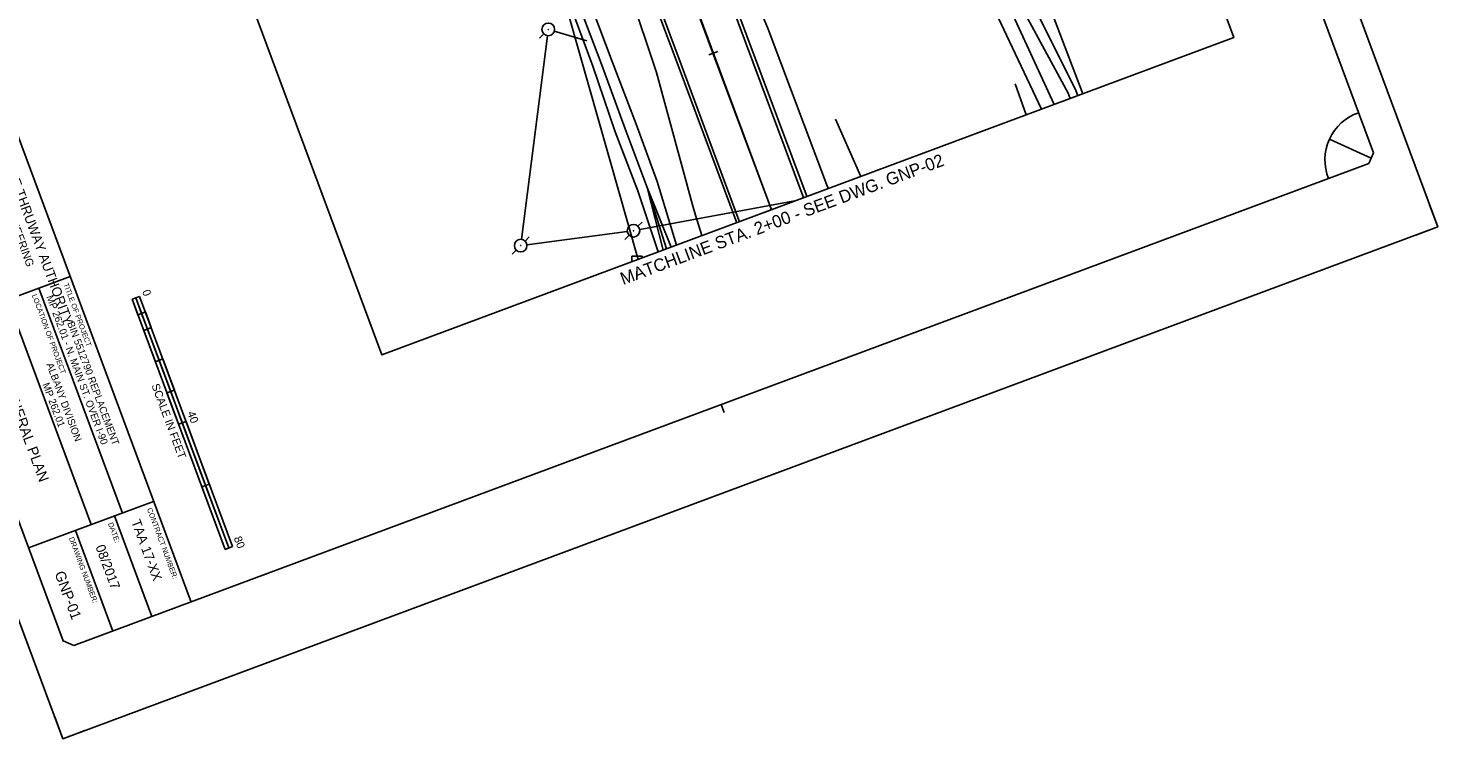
# Model space of a CAD drawing. Extents: x 1040172 to 1040822, y 1127790 to 1128580.
# Drawn here: x 1040398.7 to 1040821.5, y 1127789.6 to 1128002.5 of the extents above; entities that cross this region are included whole.
import ezdxf

# ---------------------------------------------------------------- set-up
doc = ezdxf.new("R2010")
doc.units = 0
for name, color, linetype in [('AC_P', 7, 'Continuous'), ('ACSRT_P', 7, 'Continuous'), ('clip boundary', 7, 'Continuous'), ('DD', 7, 'Continuous'), ('DELB', 7, 'Continuous'), ('LABL', 7, 'Continuous'), ('LELB', 7, 'Continuous'), ('MHB', 7, 'Continuous'), ('MPM', 7, 'Continuous'), ('NML_P', 7, 'Continuous'), ('NML_P_T', 7, 'Continuous'), ('NSB_P', 7, 'Continuous'), ('O_Details_Text Title and Subtitle Proposed_P_T', 7, 'Continuous'), ('PE', 7, 'Continuous'), ('RDU', 7, 'Continuous'), ('SHEET_BORDER', 7, 'Continuous'), ('SHEET_BORDER_CUT', 7, 'Continuous'), ('SHEET_BORDER_TEXT', 7, 'Continuous'), ('STPBY', 7, 'Continuous'), ('STSEW', 7, 'Continuous'), ('UEO', 7, 'Continuous'), ('UP', 7, 'Continuous'), ('UPGW', 7, 'Continuous')]:
    doc.layers.add(name, color=color, linetype=linetype)

msp = doc.modelspace()

# ---------------------------------------------------------------- linework, layer by layer
at = {"layer": 'AC_P'}
msp.add_line((1040551.95, 1128135.59), (1040621.67, 1127948.13), dxfattribs=at)
at = {"layer": 'ACSRT_P'}
for points in [[(1040605.59, 1127995.5), (1040602.89, 1127994.5)], [(1040623.92, 1127948.97), (1040619.42, 1127947.3)]]:
    msp.add_lwpolyline(points, dxfattribs=at)
at = {"layer": 'clip boundary'}
for points in [[(1040584.48, 1128580.33), (1040821.52, 1127942.99), (1040409.12, 1127789.61), (1040172.08, 1128426.95)], [(1040311.42, 1128424.61), (1040504.79, 1127904.67), (1040760.34, 1127999.71), (1040566.96, 1128519.66)]]:
    msp.add_lwpolyline(points, close=True, dxfattribs=at)
at = {"layer": 'DD'}
msp.add_lwpolyline([(1040590.16, 1127936.41), (1040584.34, 1127954.8), (1040577.73, 1127972.42), (1040570.66, 1127991.71), (1040562.32, 1128013.81), (1040557.05, 1128034.44), (1040549.61, 1128054.25), (1040542.46, 1128077.69), (1040533.08, 1128100.98), (1040522.95, 1128126.72), (1040518.21, 1128143.72), (1040509.19, 1128174.67), (1040500.96, 1128197.49), (1040493.5, 1128216.61), (1040486.01, 1128239.31), (1040476.77, 1128264.06), (1040465.21, 1128292.91), (1040456.76, 1128312.61), (1040439.7, 1128341.45), (1040438.14, 1128345.77)], dxfattribs=at)
at = {"layer": 'DELB'}
for points in [[(1040702.66, 1127978.26), (1040686.91, 1128011.53), (1040691.97, 1128016.01), (1040697.9, 1128014.08), (1040712.9, 1127984.14), (1040713.54, 1127982.3)], [(1040706.5, 1127979.69), (1040692.31, 1128010.21), (1040693.73, 1128012), (1040695.25, 1128011.56), (1040710.7, 1127983.05), (1040711.25, 1127981.45)]]:
    msp.add_lwpolyline(points, dxfattribs=at)
at = {"layer": 'LABL'}
msp.add_lwpolyline([(1040425.91, 1128368.18), (1040444.53, 1128309.71), (1040463.02, 1128257.15), (1040477.81, 1128216.23), (1040494.07, 1128178.95), (1040522.79, 1128098.94), (1040535.3, 1128073.89), (1040559.97, 1128013.01), (1040568.12, 1127991.17), (1040574.76, 1127971.48), (1040581.61, 1127953.82), (1040587.68, 1127935.49)], dxfattribs=at)
at = {"layer": 'LELB'}
for points in [[(1040593.2, 1127937.55), (1040587.34, 1127956.62), (1040581.09, 1127973.78), (1040573.86, 1127992.53), (1040565.61, 1128014.66), (1040560.09, 1128035.33), (1040553.1, 1128055.45), (1040545.54, 1128078.74), (1040536.49, 1128101.98), (1040528.25, 1128126.98), (1040521.57, 1128144.94), (1040511.66, 1128175.43), (1040503.47, 1128198.65), (1040496.47, 1128217.58), (1040488.54, 1128240.6), (1040478.6, 1128264.98), (1040468.18, 1128294)], [(1040587.68, 1127935.49), (1040581.61, 1127953.82), (1040574.76, 1127971.48), (1040568.12, 1127991.17), (1040559.97, 1128013.01), (1040554.52, 1128033.3)], [(1040589.16, 1127936.04), (1040584.34, 1127954.8)], [(1040591.53, 1127936.92), (1040584.34, 1127954.8)]]:
    msp.add_lwpolyline(points, dxfattribs=at)
at = {"layer": 'MHB'}
for points in [[(1040581.63, 1127933.24), (1040555, 1128027.07), (1040529.93, 1128094.57), (1040509.19, 1128193.54)], [(1040594.84, 1128145.74), (1040609.62, 1128124.16), (1040630.41, 1128039.61), (1040689.32, 1128050.28), (1040715.1, 1127982.88)]]:
    msp.add_lwpolyline(points, dxfattribs=at)
at = {"layer": 'MPM'}
for p, q in [((1040579.77, 1127932.55), (1040579.77, 1127934.24)), ((1040579.77, 1127934.24), (1040582.92, 1127934.24)), ((1040582.92, 1127934.24), (1040582.92, 1127933.72))]:
    msp.add_line(p, q, dxfattribs=at)
at = {"layer": 'NML_P'}
msp.add_line((1040504.79, 1127904.67), (1040760.34, 1127999.71), dxfattribs=at)
at = {"layer": 'NSB_P'}
for p, q in [((1040429.88, 1127921.35), (1040432.13, 1127922.18)), ((1040431.01, 1127921.76), (1040429.88, 1127921.35)), ((1040429.88, 1127921.35), (1040457.77, 1127846.36)), ((1040429.88, 1127921.35), (1040431.63, 1127916.66)), ((1040431.01, 1127921.76), (1040458.9, 1127846.78)), ((1040432.75, 1127917.08), (1040431.01, 1127921.76)), ((1040432.13, 1127922.18), (1040460.02, 1127847.2)), ((1040431.63, 1127916.66), (1040433.88, 1127917.5)), ((1040433.88, 1127917.5), (1040432.75, 1127917.08)), ((1040435.62, 1127912.81), (1040433.88, 1127917.5)), ((1040431.63, 1127916.66), (1040432.75, 1127917.08)), ((1040432.75, 1127917.08), (1040434.49, 1127912.39)), ((1040433.37, 1127911.97), (1040435.62, 1127912.81)), ((1040434.49, 1127912.39), (1040433.37, 1127911.97)), ((1040433.37, 1127911.97), (1040436.86, 1127902.6)), ((1040434.49, 1127912.39), (1040435.62, 1127912.81)), ((1040437.98, 1127903.02), (1040434.49, 1127912.39)), ((1040436.86, 1127902.6), (1040439.11, 1127903.44)), ((1040436.86, 1127902.6), (1040437.98, 1127903.02)), ((1040439.11, 1127903.44), (1040437.98, 1127903.02)), ((1040437.98, 1127903.02), (1040441.47, 1127893.65)), ((1040442.59, 1127894.06), (1040439.11, 1127903.44)), ((1040440.34, 1127893.23), (1040442.59, 1127894.06)), ((1040441.47, 1127893.65), (1040440.34, 1127893.23)), ((1040440.34, 1127893.23), (1040443.83, 1127883.85)), ((1040441.47, 1127893.65), (1040442.59, 1127894.06)), ((1040444.95, 1127884.27), (1040441.47, 1127893.65)), ((1040443.83, 1127883.85), (1040446.08, 1127884.69)), ((1040443.83, 1127883.85), (1040444.95, 1127884.27)), ((1040446.08, 1127884.69), (1040444.95, 1127884.27)), ((1040444.95, 1127884.27), (1040451.92, 1127865.53)), ((1040453.05, 1127865.95), (1040446.08, 1127884.69)), ((1040450.8, 1127865.11), (1040453.05, 1127865.95)), ((1040451.92, 1127865.53), (1040450.8, 1127865.11)), ((1040450.8, 1127865.11), (1040457.77, 1127846.36)), ((1040451.92, 1127865.53), (1040453.05, 1127865.95)), ((1040458.9, 1127846.78), (1040451.92, 1127865.53)), ((1040457.77, 1127846.36), (1040460.02, 1127847.2)), ((1040457.77, 1127846.36), (1040458.9, 1127846.78))]:
    msp.add_line(p, q, dxfattribs=at)
at = {"layer": 'PE'}
for points in [[(1040439.24, 1128472.16), (1040441.33, 1128466.57), (1040458.94, 1128419.35), (1040476.26, 1128371.77), (1040493.04, 1128326.48), (1040510.61, 1128278.87), (1040527.62, 1128233.22), (1040545.23, 1128186.41), (1040562.42, 1128139.9), (1040579.67, 1128093.09), (1040596.97, 1128046.17), (1040614.6, 1127999.47), (1040632.03, 1127952.66), (1040632.25, 1127952.07)], [(1040611.22, 1127944.25), (1040611.04, 1127944.71), (1040593.69, 1127991.31), (1040575.95, 1128038.43), (1040558.63, 1128085.25), (1040541.53, 1128131.54), (1040524.14, 1128178.42), (1040506.77, 1128224.73), (1040489.58, 1128270.79), (1040472.04, 1128318.16), (1040455.43, 1128363.98), (1040438.41, 1128410.32), (1040420.58, 1128458.47), (1040418.37, 1128464.39)]]:
    msp.add_lwpolyline(points, dxfattribs=at)
at = {"layer": 'RDU'}
for points in [[(1040442.34, 1128473.31), (1040444.42, 1128467.6), (1040461.41, 1128420.47), (1040479.69, 1128373.54), (1040484.11, 1128363.91), (1040487.49, 1128353.45), (1040496.23, 1128327.89), (1040514.27, 1128279.94), (1040530.58, 1128234.37), (1040548.36, 1128187.4), (1040565.14, 1128141.04), (1040582.73, 1128094.4), (1040600.59, 1128047.69), (1040609.21, 1128026.55), (1040611.78, 1128023.8), (1040620.64, 1128002.21), (1040638.45, 1127955.04), (1040638.78, 1127954.5)], [(1040600.82, 1127940.38), (1040598.84, 1127946.51), (1040597.95, 1127949.62), (1040587.15, 1127989.28), (1040571.28, 1128036.76), (1040553.79, 1128083.5), (1040537.46, 1128130.34), (1040520.2, 1128176.84), (1040503.11, 1128223.36), (1040485.75, 1128269.45), (1040468.45, 1128317.03), (1040451.55, 1128362.66), (1040435.14, 1128409.38), (1040417.07, 1128457.26), (1040414.87, 1128463.09)]]:
    msp.add_lwpolyline(points, dxfattribs=at)
at = {"layer": 'SHEET_BORDER'}
for p, q in [((1040447.57, 1127830.58), (1040330.5, 1128145.33)), ((1040417.6, 1127853.77), (1040367.49, 1127988.51)), ((1040411.29, 1127928.11), (1040373.8, 1127914.17)), ((1040426.97, 1127857.26), (1040401.92, 1127924.63)), ((1040606.61, 1127889.73), (1040607.48, 1127887.39)), ((1040398.85, 1127846.8), (1040436.35, 1127860.75)), ((1040435.85, 1127826.22), (1040424.63, 1127856.39)), ((1040424.13, 1127821.86), (1040412.91, 1127852.03))]:
    msp.add_line(p, q, dxfattribs=at)
msp.add_lwpolyline([(1040412.42, 1127817.51), (1040409.2, 1127818.98), (1040191.33, 1128404.77), (1040192.81, 1128407.99), (1040581.19, 1128552.44), (1040584.4, 1128550.96), (1040802.27, 1127965.17), (1040800.8, 1127961.95)], close=True, dxfattribs=at)
msp.add_lwpolyline([(1040801.54, 1127963.56), (1040789.22, 1127969.2)], dxfattribs=at)
msp.add_arc((1040802.45, 1127963.14), 14.79, 108.3228, 202.4794, dxfattribs=at)
at = {"layer": 'SHEET_BORDER_CUT'}
msp.add_lwpolyline([(1040172.08, 1128426.95), (1040409.12, 1127789.61), (1040821.52, 1127942.99), (1040584.48, 1128580.33)], close=True, dxfattribs=at)
for points in [[(1040819.06, 1127949.61), (1040821.52, 1127942.99), (1040814.9, 1127940.52)], [(1040415.75, 1127792.07), (1040409.12, 1127789.61), (1040406.66, 1127796.23)]]:
    msp.add_lwpolyline(points, dxfattribs=at)
at = {"layer": 'SHEET_BORDER_TEXT'}
msp.add_line((1040409.12, 1127789.61), (1040409.12, 1127789.61), dxfattribs=at)
at = {"layer": 'STPBY'}
msp.add_lwpolyline([(1040621.67, 1127948.13), (1040621.55, 1127948.45), (1040603.98, 1127995.3), (1040586.61, 1128042.26), (1040569.27, 1128089.08), (1040551.95, 1128135.59), (1040534.57, 1128182.32), (1040517.18, 1128229.1), (1040500.26, 1128274.64), (1040482.6, 1128322.04), (1040465.84, 1128367.81), (1040448.53, 1128414.76), (1040430.74, 1128462.77), (1040428.7, 1128468.23)], dxfattribs=at)
at = {"layer": 'STSEW'}
for points in [[(1040438.27, 1128471.79), (1040440.35, 1128466.17), (1040457.9, 1128418.91), (1040475.34, 1128371.42), (1040492.13, 1128326.1), (1040509.73, 1128278.49), (1040526.79, 1128232.92), (1040544.25, 1128186.02), (1040561.46, 1128139.5), (1040578.77, 1128092.69), (1040596.13, 1128045.88), (1040613.59, 1127999.12), (1040631.02, 1127952.26), (1040631.23, 1127951.69)], [(1040612.07, 1127944.56), (1040611.89, 1127945.04), (1040594.53, 1127991.69), (1040577, 1128038.8), (1040559.65, 1128085.64), (1040542.56, 1128131.85), (1040525.02, 1128178.93), (1040507.92, 1128225.11), (1040490.75, 1128271.15), (1040473.24, 1128318.19), (1040456.29, 1128364.36), (1040439.27, 1128410.63), (1040421.37, 1128458.89), (1040419.2, 1128464.7)]]:
    msp.add_lwpolyline(points, dxfattribs=at)
at = {"layer": 'UEO'}
for points in [[(1040546.68, 1127939.26), (1040554.47, 1128000.28)], [(1040582.13, 1127942.18), (1040629.18, 1127950.93)], [(1040548.32, 1127937.63), (1040578.4, 1127941.59)]]:
    msp.add_lwpolyline(points, dxfattribs=at)
at = {"layer": 'UP'}
for p, q in [((1040554.78, 1128002.16), (1040554.65, 1128002.16)), ((1040554.71, 1128002.22), (1040554.71, 1128002.09)), ((1040553.38, 1128000.82), (1040552.13, 1127999.56)), ((1040581.6, 1127943.18), (1040582.85, 1127944.43)), ((1040547.77, 1127938.72), (1040549.02, 1127939.98)), ((1040578.94, 1127940.49), (1040577.69, 1127939.24)), ((1040580.33, 1127941.84), (1040580.21, 1127941.84)), ((1040580.27, 1127941.9), (1040580.27, 1127941.77)), ((1040545.11, 1127936.04), (1040543.86, 1127934.78)), ((1040546.5, 1127937.38), (1040546.38, 1127937.38)), ((1040546.44, 1127937.44), (1040546.44, 1127937.32))]:
    msp.add_line(p, q, dxfattribs=at)
for centre in [(1040554.71, 1128002.16), (1040580.27, 1127941.84), (1040546.44, 1127937.38)]:
    msp.add_circle(centre, 1.89, dxfattribs=at)
at = {"layer": 'UPGW'}
for points in [[(1040566.27, 1127998.75), (1040556.53, 1128001.62)], [(1040694.71, 1127985.9), (1040698.04, 1127976.54)], [(1040640.9, 1127975.31), (1040648.51, 1127958.12)]]:
    msp.add_lwpolyline(points, dxfattribs=at)

# ---------------------------------------------------------------- texts
at = {"layer": 'NML_P_T'}
msp.add_text('MATCHLINE STA. 2+00 - SEE DWG. GNP-02', height=3.744, rotation=20.4011, dxfattribs=at).set_placement((1040577.15, 1127925.55))
at = {"layer": 'NSB_P'}
for s, p in [('0', (1040432.86, 1127923.67)), ('SCALE IN FEET', (1040435.65, 1127895.51)), ('40', (1040446.4, 1127887.25)), ('80', (1040460.35, 1127849.76))]:
    msp.add_text(s, height=2.4, rotation=290.4011, dxfattribs=at).set_placement(p)
at = {"layer": 'O_Details_Text Title and Subtitle Proposed_P_T'}
for s, height, p in [('GENERAL PLAN', 3.1248, (1040390.95, 1127896.28)), ('GNP-01', 3.125, (1040406.59, 1127839.17))]:
    msp.add_text(s, height=height, rotation=290.4011, dxfattribs=at).set_placement(p)
at = {"layer": 'SHEET_BORDER'}
for s, height, p in [('NEW YORK STATE THRUWAY AUTHORITY', 2.88, (1040382.28, 1127986.82)), ('DEPARTMENT OF ENGINEERING', 2.4, (1040380.64, 1127978.4)), ('TITLE OF PROJECT', 1.5625, (1040409.27, 1127925.82)), ('LOCATION OF PROJECT', 1.5625, (1040399.8, 1127922.49)), ('CONTRACT NUMBER:', 1.5625, (1040434.32, 1127858.46)), ('DATE:', 1.563, (1040422.61, 1127854.1)), ('DRAWING NUMBER:', 1.5625, (1040410.89, 1127849.74))]:
    msp.add_text(s, height=height, rotation=290.4011, dxfattribs=at).set_placement(p)
at = {"layer": 'SHEET_BORDER_TEXT'}
for s, height, p in [('MP 262.01 - N. MAIN ST. OVER I-90', 2.16, (1040404.13, 1127922.06)), ('BIN 5512790 REPLACEMENT', 2.16, (1040410.39, 1127914.18)), ('ALBANY DIVISION', 2.16, (1040404.16, 1127901.77)), ('MP 262.01', 2.16, (1040402.97, 1127895.84)), ('TAA 17-XX', 2.88, (1040429.55, 1127854.69)), ('08/2017', 2.88, (1040418.84, 1127847.13))]:
    msp.add_text(s, height=height, rotation=290.4011, dxfattribs=at).set_placement(p)

doc.saveas('drawing.dxf')
